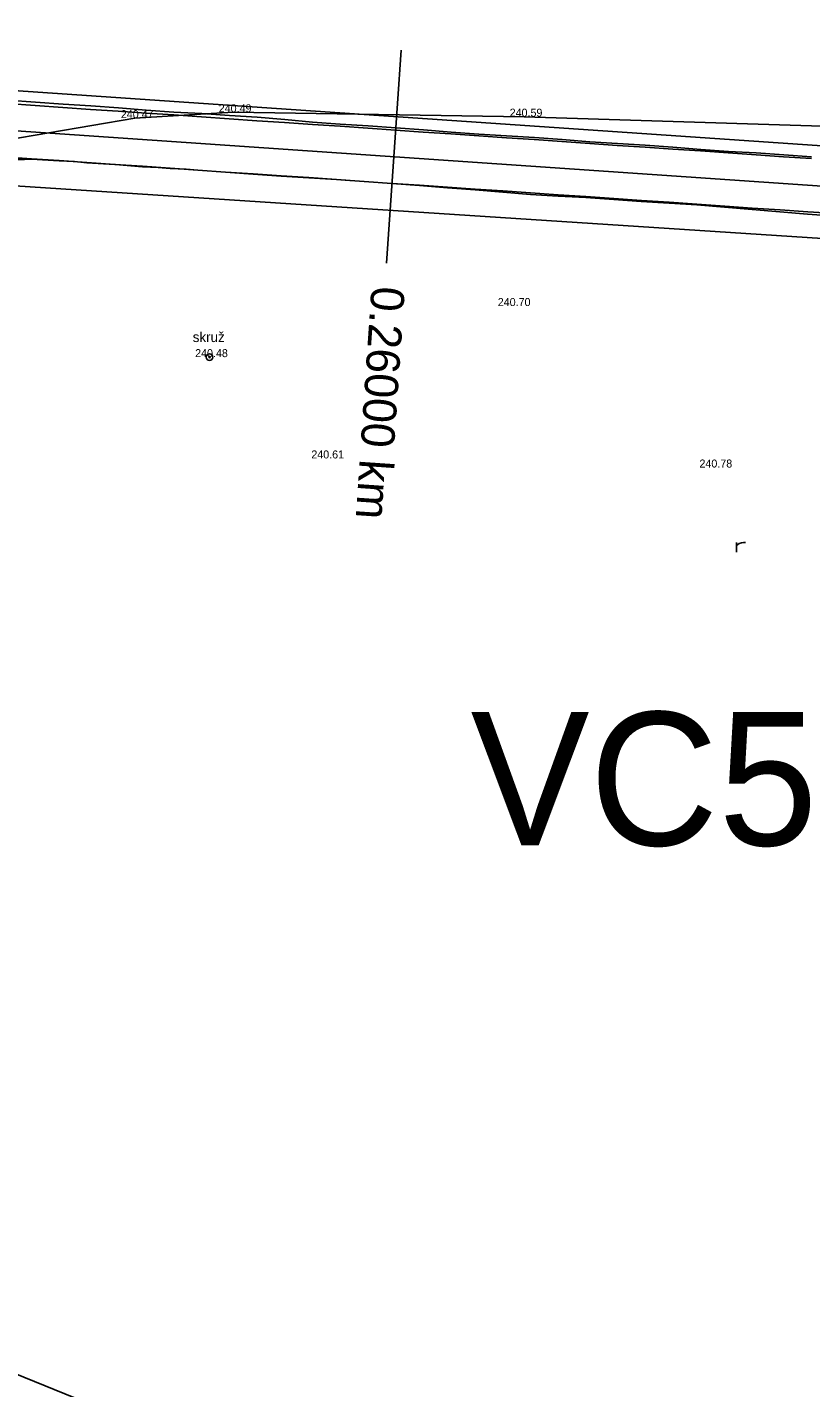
# Model space of a CAD drawing. Extents: x -555887 to -552101, y -1100251 to -1096546.
# Drawn here: x -554448.2 to -554389.4, y -1098460 to -1098358 of the extents above; entities that cross this region are included whole.
import ezdxf

# ---------------------------------------------------------------- set-up
doc = ezdxf.new("R2010")
doc.units = 0
for name, color, linetype in [('PARCELY_cesty', 7, 'Continuous'), ('POLYGONY_POPIS_CESTY', 7, 'Continuous'), ('POLYGONY_SITUACE_PF', 7, 'Continuous'), ('POLYGONY_SITUACE_PF_POPISY', 7, 'Continuous'), ('POLYGONY_SITUACE_PO', 7, 'Continuous'), ('vrstevnice', 7, 'Continuous'), ('Výškopis', 7, 'Continuous'), ('ZSST', 7, 'Continuous'), ('zájem', 7, 'Continuous')]:
    doc.layers.add(name, color=color, linetype=linetype)

msp = doc.modelspace()

# ---------------------------------------------------------------- linework, layer by layer
at = {"layer": 'PARCELY_cesty'}
msp.add_lwpolyline([(-554666.58, -1098424.3), (-554661.61, -1098426.35), (-554474.62, -1098365.56), (-554470, -1098364.25), (-554462.92, -1098363), (-554455.97, -1098362.75), (-554451.05, -1098362.62), (-554296.95, -1098373.16), (-554290.89, -1098371.6), (-554270.39, -1098373.3), (-554264.04, -1098376.17), (-554253.34, -1098377.56), (-554081.03, -1098403.4), (-554065.66, -1098405.31), (-554039.82, -1098406.01), (-554011.2, -1098408.42), (-553994.13, -1098410.89)], dxfattribs=at)
at = {"layer": 'POLYGONY_SITUACE_PF'}
for p, q in [((-554420.15, -1098359.72), (-554420.7, -1098367.7)), ((-554420.7, -1098367.7), (-554421.25, -1098375.69))]:
    msp.add_line(p, q, dxfattribs=at)
at = {"layer": 'POLYGONY_SITUACE_PO'}
for p, q in [((-554449.64, -1098363.45), (-554447.57, -1098363.61)), ((-554449.66, -1098363.72), (-554447.58, -1098363.86)), ((-554449.66, -1098363.72), (-554447.58, -1098363.86)), ((-554447.58, -1098363.86), (-554445.51, -1098364)), ((-554447.58, -1098363.86), (-554445.51, -1098364)), ((-554447.57, -1098363.61), (-554445.49, -1098363.76)), ((-554445.51, -1098364), (-554443.43, -1098364.15)), ((-554445.51, -1098364), (-554443.43, -1098364.15)), ((-554445.49, -1098363.76), (-554443.41, -1098363.88)), ((-554443.43, -1098364.15), (-554441.35, -1098364.29)), ((-554443.43, -1098364.15), (-554441.35, -1098364.29)), ((-554443.41, -1098363.88), (-554441.33, -1098364.03)), ((-554441.35, -1098364.29), (-554439.27, -1098364.43)), ((-554441.35, -1098364.29), (-554439.27, -1098364.43)), ((-554441.33, -1098364.03), (-554439.26, -1098364.22)), ((-554439.27, -1098364.43), (-554437.19, -1098364.57)), ((-554439.27, -1098364.43), (-554437.19, -1098364.57)), ((-554439.26, -1098364.22), (-554437.18, -1098364.35)), ((-554437.19, -1098364.57), (-554435.11, -1098364.71)), ((-554437.19, -1098364.57), (-554435.11, -1098364.71)), ((-554437.18, -1098364.35), (-554435.1, -1098364.47)), ((-554435.1, -1098364.47), (-554433.02, -1098364.6)), ((-554435.11, -1098364.71), (-554433.03, -1098364.86)), ((-554435.11, -1098364.71), (-554433.03, -1098364.86)), ((-554433.03, -1098364.86), (-554430.96, -1098365)), ((-554433.03, -1098364.86), (-554430.96, -1098365)), ((-554433.02, -1098364.6), (-554430.94, -1098364.74)), ((-554430.96, -1098365), (-554428.88, -1098365.14)), ((-554430.96, -1098365), (-554428.88, -1098365.14)), ((-554430.94, -1098364.74), (-554428.86, -1098364.9)), ((-554428.88, -1098365.14), (-554426.8, -1098365.28)), ((-554428.88, -1098365.14), (-554426.8, -1098365.28)), ((-554428.86, -1098364.9), (-554426.79, -1098365.11)), ((-554426.8, -1098365.28), (-554424.72, -1098365.42)), ((-554426.8, -1098365.28), (-554424.72, -1098365.42)), ((-554426.79, -1098365.11), (-554424.71, -1098365.25)), ((-554424.72, -1098365.42), (-554422.64, -1098365.57)), ((-554424.72, -1098365.42), (-554422.64, -1098365.57)), ((-554424.71, -1098365.25), (-554422.63, -1098365.39)), ((-554422.64, -1098365.57), (-554420.56, -1098365.71)), ((-554422.64, -1098365.57), (-554420.56, -1098365.71)), ((-554422.63, -1098365.39), (-554420.55, -1098365.54)), ((-554420.55, -1098365.54), (-554418.47, -1098365.68)), ((-554451.1, -1098365.63), (-554287.2, -1098376.83)), ((-554420.56, -1098365.71), (-554418.49, -1098365.85)), ((-554420.56, -1098365.71), (-554418.49, -1098365.85)), ((-554418.49, -1098365.85), (-554416.41, -1098365.99)), ((-554418.49, -1098365.85), (-554416.41, -1098365.99)), ((-554418.47, -1098365.68), (-554416.4, -1098365.85)), ((-554416.41, -1098365.99), (-554414.33, -1098366.14)), ((-554416.41, -1098365.99), (-554414.33, -1098366.14)), ((-554416.4, -1098365.85), (-554414.32, -1098366)), ((-554414.33, -1098366.14), (-554412.25, -1098366.28)), ((-554414.33, -1098366.14), (-554412.25, -1098366.28)), ((-554414.32, -1098366), (-554412.24, -1098366.14)), ((-554412.25, -1098366.28), (-554410.17, -1098366.42)), ((-554412.25, -1098366.28), (-554410.17, -1098366.42)), ((-554412.24, -1098366.14), (-554410.16, -1098366.27)), ((-554410.17, -1098366.42), (-554408.09, -1098366.56)), ((-554410.17, -1098366.42), (-554408.09, -1098366.56)), ((-554410.16, -1098366.27), (-554408.08, -1098366.41)), ((-554408.09, -1098366.56), (-554406.01, -1098366.7)), ((-554408.09, -1098366.56), (-554406.01, -1098366.7)), ((-554408.08, -1098366.41), (-554406.01, -1098366.58)), ((-554406.01, -1098366.58), (-554403.93, -1098366.72)), ((-554406.01, -1098366.7), (-554403.94, -1098366.85)), ((-554406.01, -1098366.7), (-554403.94, -1098366.85)), ((-554403.94, -1098366.85), (-554401.86, -1098366.99)), ((-554403.94, -1098366.85), (-554401.86, -1098366.99)), ((-554403.93, -1098366.72), (-554401.85, -1098366.84)), ((-554401.86, -1098366.99), (-554399.78, -1098367.13)), ((-554401.86, -1098366.99), (-554399.78, -1098367.13)), ((-554401.85, -1098366.84), (-554399.77, -1098366.99)), ((-554399.78, -1098367.13), (-554397.7, -1098367.27)), ((-554399.78, -1098367.13), (-554397.7, -1098367.27)), ((-554399.77, -1098366.99), (-554397.69, -1098367.15)), ((-554397.7, -1098367.27), (-554395.62, -1098367.41)), ((-554397.7, -1098367.27), (-554395.62, -1098367.41)), ((-554397.69, -1098367.15), (-554395.61, -1098367.31)), ((-554395.62, -1098367.41), (-554393.54, -1098367.56)), ((-554395.62, -1098367.41), (-554393.54, -1098367.56)), ((-554395.61, -1098367.31), (-554393.53, -1098367.42)), ((-554393.54, -1098367.56), (-554391.47, -1098367.7)), ((-554393.54, -1098367.56), (-554391.47, -1098367.7)), ((-554393.53, -1098367.42), (-554391.46, -1098367.57)), ((-554391.46, -1098367.57), (-554389.38, -1098367.7)), ((-554449.95, -1098367.95), (-554447.86, -1098367.85)), ((-554449.95, -1098367.99), (-554447.86, -1098367.89)), ((-554449.94, -1098367.71), (-554447.86, -1098367.85)), ((-554447.86, -1098367.85), (-554445.78, -1098367.99)), ((-554447.86, -1098367.85), (-554445.78, -1098367.99)), ((-554447.86, -1098367.89), (-554445.78, -1098368.01)), ((-554445.78, -1098367.99), (-554443.7, -1098368.14)), ((-554445.78, -1098367.99), (-554443.7, -1098368.14)), ((-554445.78, -1098368.01), (-554444.64, -1098368.07)), ((-554444.64, -1098368.07), (-554443.7, -1098368.15)), ((-554443.7, -1098368.14), (-554441.62, -1098368.28)), ((-554443.7, -1098368.14), (-554441.62, -1098368.28)), ((-554443.7, -1098368.15), (-554441.62, -1098368.28)), ((-554441.62, -1098368.28), (-554439.54, -1098368.42)), ((-554441.62, -1098368.28), (-554441.56, -1098368.28)), ((-554441.62, -1098368.28), (-554439.54, -1098368.42)), ((-554441.56, -1098368.28), (-554439.54, -1098368.45)), ((-554439.54, -1098368.42), (-554437.46, -1098368.56)), ((-554439.54, -1098368.42), (-554437.46, -1098368.56)), ((-554439.54, -1098368.45), (-554438.37, -1098368.5)), ((-554438.37, -1098368.5), (-554437.47, -1098368.59)), ((-554437.47, -1098368.59), (-554436.27, -1098368.64)), ((-554437.46, -1098368.56), (-554435.39, -1098368.71)), ((-554437.46, -1098368.56), (-554435.39, -1098368.71)), ((-554436.27, -1098368.64), (-554435.39, -1098368.72)), ((-554391.47, -1098367.7), (-554389.39, -1098367.84)), ((-554391.47, -1098367.7), (-554389.39, -1098367.84)), ((-554435.39, -1098368.71), (-554433.31, -1098368.85)), ((-554435.39, -1098368.71), (-554433.31, -1098368.85)), ((-554435.39, -1098368.72), (-554433.31, -1098368.87)), ((-554433.31, -1098368.85), (-554431.23, -1098368.99)), ((-554433.31, -1098368.85), (-554431.23, -1098368.99)), ((-554433.31, -1098368.87), (-554431.23, -1098369.01)), ((-554431.23, -1098368.99), (-554429.15, -1098369.13)), ((-554431.23, -1098368.99), (-554429.15, -1098369.13)), ((-554431.23, -1098369.01), (-554429.15, -1098369.15)), ((-554429.15, -1098369.13), (-554427.07, -1098369.27)), ((-554429.15, -1098369.13), (-554427.07, -1098369.27)), ((-554429.15, -1098369.15), (-554427.07, -1098369.28)), ((-554427.07, -1098369.27), (-554424.99, -1098369.42)), ((-554427.07, -1098369.27), (-554424.99, -1098369.42)), ((-554427.07, -1098369.28), (-554424.99, -1098369.42)), ((-554424.99, -1098369.42), (-554422.92, -1098369.56)), ((-554424.99, -1098369.42), (-554424.35, -1098369.46)), ((-554424.99, -1098369.42), (-554422.92, -1098369.56)), ((-554424.35, -1098369.46), (-554422.92, -1098369.56)), ((-554422.92, -1098369.56), (-554420.84, -1098369.7)), ((-554422.92, -1098369.56), (-554420.84, -1098369.7)), ((-554422.92, -1098369.56), (-554420.84, -1098369.7)), ((-554420.84, -1098369.7), (-554418.76, -1098369.84)), ((-554420.84, -1098369.7), (-554418.76, -1098369.85)), ((-554420.84, -1098369.7), (-554418.76, -1098369.84)), ((-554418.76, -1098369.84), (-554416.68, -1098369.98)), ((-554418.76, -1098369.84), (-554416.68, -1098369.98)), ((-554418.76, -1098369.85), (-554416.68, -1098370.04)), ((-554416.68, -1098369.98), (-554414.6, -1098370.13)), ((-554416.68, -1098369.98), (-554414.6, -1098370.13)), ((-554416.68, -1098370.04), (-554414.6, -1098370.18)), ((-554414.6, -1098370.13), (-554412.52, -1098370.27)), ((-554414.6, -1098370.13), (-554412.52, -1098370.27)), ((-554414.6, -1098370.18), (-554412.53, -1098370.35)), ((-554412.53, -1098370.35), (-554410.45, -1098370.54)), ((-554412.52, -1098370.27), (-554410.44, -1098370.41)), ((-554412.52, -1098370.27), (-554410.44, -1098370.41)), ((-554410.45, -1098370.54), (-554408.37, -1098370.66)), ((-554410.44, -1098370.41), (-554408.37, -1098370.55)), ((-554410.44, -1098370.41), (-554408.37, -1098370.55)), ((-554408.37, -1098370.55), (-554406.29, -1098370.69)), ((-554408.37, -1098370.55), (-554406.29, -1098370.69)), ((-554408.37, -1098370.66), (-554406.29, -1098370.76)), ((-554406.29, -1098370.69), (-554404.21, -1098370.84)), ((-554406.29, -1098370.69), (-554404.21, -1098370.84)), ((-554406.29, -1098370.76), (-554404.21, -1098370.92)), ((-554404.21, -1098370.84), (-554402.13, -1098370.98)), ((-554404.21, -1098370.84), (-554402.13, -1098370.98)), ((-554404.21, -1098370.92), (-554402.14, -1098371.06)), ((-554402.14, -1098371.06), (-554400.06, -1098371.19)), ((-554402.13, -1098370.98), (-554400.05, -1098371.12)), ((-554402.13, -1098370.98), (-554400.05, -1098371.12)), ((-554400.06, -1098371.19), (-554397.98, -1098371.32)), ((-554400.05, -1098371.12), (-554397.97, -1098371.26)), ((-554400.05, -1098371.12), (-554397.97, -1098371.26)), ((-554397.98, -1098371.32), (-554395.9, -1098371.49)), ((-554397.97, -1098371.26), (-554395.89, -1098371.41)), ((-554397.97, -1098371.26), (-554395.89, -1098371.41)), ((-554395.9, -1098371.49), (-554393.82, -1098371.66)), ((-554395.89, -1098371.41), (-554393.82, -1098371.55)), ((-554395.89, -1098371.41), (-554393.82, -1098371.55)), ((-554393.82, -1098371.55), (-554391.74, -1098371.69)), ((-554393.82, -1098371.55), (-554391.74, -1098371.69)), ((-554393.82, -1098371.66), (-554391.75, -1098371.84)), ((-554391.74, -1098371.69), (-554389.66, -1098371.83)), ((-554391.74, -1098371.69), (-554389.66, -1098371.83)), ((-554391.75, -1098371.84), (-554389.67, -1098372.02)), ((-554389.67, -1098372.02), (-554387.59, -1098372.15)), ((-554389.66, -1098371.83), (-554387.58, -1098371.97)), ((-554389.66, -1098371.83), (-554387.58, -1098371.97))]:
    msp.add_line(p, q, dxfattribs=at)
at = {"layer": 'vrstevnice'}
msp.add_lwpolyline([(-554522.95, -1098432.12), (-554492.28, -1098436.31), (-554460.21, -1098454.44), (-554415.59, -1098472.57), (-554357.03, -1098493.49), (-554288.71, -1098499.07), (-554230.77, -1098502.48)], dxfattribs=at)
at = {"layer": 'ZSST'}
for points in [[(-554664.51, -1098427.29), (-554593.24, -1098405.5), (-554564.12, -1098396.39), (-554504.51, -1098380.38), (-554474.09, -1098371.8), (-554453.04, -1098367.02), (-554440.1, -1098364.81), (-554432.74, -1098364.37), (-554410.92, -1098364.7), (-554369.44, -1098366), (-554333.38, -1098368), (-554270.17, -1098373.82), (-554215.58, -1098380.33), (-554205.6, -1098382.24), (-554194.57, -1098383.81), (-554169.13, -1098388.36), (-554184.13, -1098381.1), (-554194.68, -1098382.34), (-554205.5, -1098381.25), (-554215.58, -1098380.33)], [(-554395, -1098397.36), (-554395, -1098396.63)], [(-554395, -1098396.86), (-554394.9, -1098396.77), (-554394.8, -1098396.71), (-554394.64, -1098396.66), (-554394.49, -1098396.64), (-554394.33, -1098396.63)]]:
    msp.add_lwpolyline(points, dxfattribs=at)
for radius in [0.25, 0.05]:
    msp.add_circle((-554434.51, -1098382.73), radius, dxfattribs=at)
at = {"layer": 'zájem'}
for points in [[(-555057.79, -1098455.7), (-554947.91, -1098379.76), (-554868.79, -1098324.5), (-554807.83, -1098282.81), (-554734.83, -1098232.28), (-554733.03, -1098237.3), (-554723.03, -1098264.9), (-554699.69, -1098346.16), (-554674.86, -1098437.73), (-554672.03, -1098436.78), (-554666.38, -1098434.92), (-554663.87, -1098434.13), (-554584.1, -1098408.07), (-554542.63, -1098394.85), (-554461.77, -1098369.06), (-554380.5, -1098374.37), (-554285.56, -1098379.8), (-554280.9, -1098380.23), (-554271.92, -1098380.9), (-554131.79, -1098402.65)], [(-554131.79, -1098402.65), (-554271.92, -1098380.9), (-554280.9, -1098380.23), (-554285.56, -1098379.8), (-554380.5, -1098374.37), (-554461.77, -1098369.06), (-554542.63, -1098394.85), (-554584.1, -1098408.07), (-554663.87, -1098434.13), (-554666.38, -1098434.92), (-554672.03, -1098436.78), (-554674.86, -1098437.73), (-554699.69, -1098346.16), (-554723.03, -1098264.9), (-554733.03, -1098237.3), (-554734.83, -1098232.28), (-554807.83, -1098282.81), (-554868.79, -1098324.5), (-554947.91, -1098379.76), (-555057.79, -1098455.7)]]:
    msp.add_lwpolyline(points, dxfattribs=at)

# ---------------------------------------------------------------- texts
at = {"layer": 'POLYGONY_POPIS_CESTY'}
msp.add_text('VC5', height=10, dxfattribs=at).set_placement((-554414.94, -1098419.35))
at = {"layer": 'POLYGONY_SITUACE_PF_POPISY'}
msp.add_text('0.26000 km', height=2.5, rotation=266.0887, dxfattribs=at).set_placement((-554422.36, -1098377.37))
at = {"layer": 'Výškopis'}
for s, p in [('240.47', (-554441.16, -1098364.81)), ('240.49', (-554433.82, -1098364.37)), ('240.59', (-554412.01, -1098364.7)), ('240.70', (-554412.9, -1098378.9)), ('240.48', (-554435.59, -1098382.73)), ('240.61', (-554426.88, -1098390.33)), ('240.78', (-554397.78, -1098391.01))]:
    msp.add_text(s, height=0.6, dxfattribs=at).set_placement(p)
at = {"layer": 'ZSST'}
msp.add_text('skruž', height=0.75, dxfattribs=at).set_placement((-554435.77, -1098381.6))

doc.saveas('drawing.dxf')
